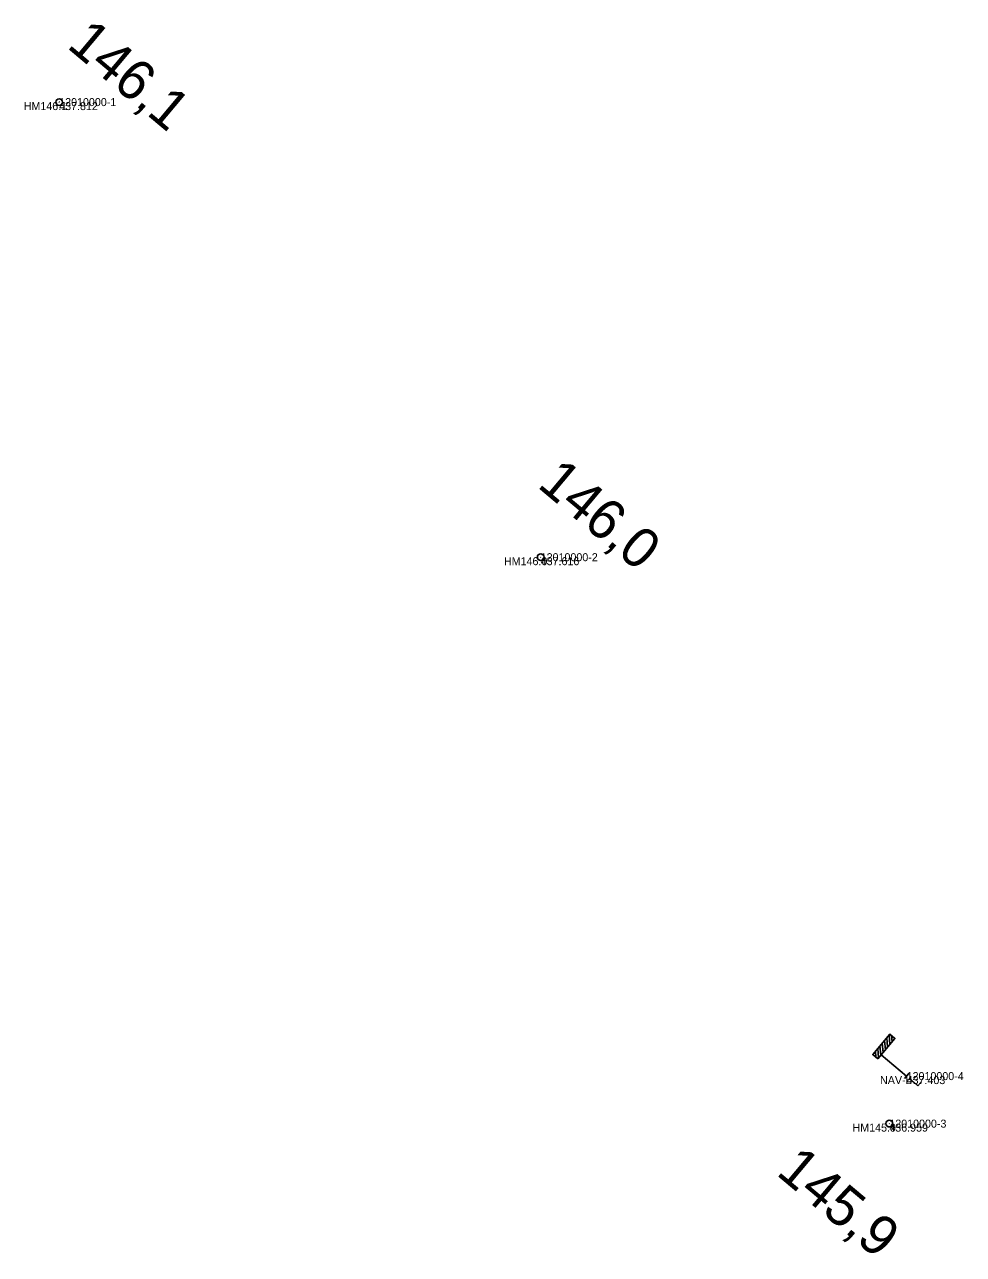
# Model space of a CAD drawing. Extents: x -653665 to -652742, y -1166300 to -1165487.
# Drawn here: x -652882.8 to -652741.9, y -1166299.9 to -1166115.5 of the extents above; entities that cross this region are included whole.
import ezdxf

# ---------------------------------------------------------------- set-up
doc = ezdxf.new("R2010")
doc.units = 0
for name, color, linetype in [('Vrstva 6', 7, 'Continuous'), ('Vrstva 60', 7, 'Continuous'), ('Vrstva 61', 7, 'Continuous'), ('Vrstva 62', 7, 'Continuous'), ('Vrstva 7', 7, 'Continuous')]:
    doc.layers.add(name, color=color, linetype=linetype)

msp = doc.modelspace()

# ---------------------------------------------------------------- linework, layer by layer
at = {"layer": 'Vrstva 6'}
for p, q in [((-652753.78, -1166267.81), (-652753.66, -1166269.22)), ((-652753.44, -1166267.4), (-652753.32, -1166268.81)), ((-652753.1, -1166266.99), (-652752.98, -1166268.4)), ((-652752.72, -1166267.09), (-652752.64, -1166268)), ((-652755.15, -1166269.43), (-652755.07, -1166270.34)), ((-652754.81, -1166269.03), (-652754.68, -1166270.43)), ((-652754.47, -1166268.62), (-652754.34, -1166270.03)), ((-652754.13, -1166268.21), (-652754, -1166269.62)), ((-652750.47, -1166273.16), (-652754.28, -1166269.96)), ((-652750.79, -1166273.54), (-652750.15, -1166272.77))]:
    msp.add_line(p, q, dxfattribs=at)
msp.add_lwpolyline([(-652754.8, -1166270.57), (-652755.56, -1166269.93), (-652752.99, -1166266.86), (-652752.23, -1166267.51)], close=True, dxfattribs=at)
at = {"layer": 'Vrstva 60'}
for p, q in [((-652877.65, -1166127.08), (-652877.65, -1166127.08)), ((-652805.39, -1166195.34), (-652805.39, -1166195.34)), ((-652750.47, -1166273.16), (-652750.47, -1166273.16)), ((-652753.07, -1166280.29), (-652753.07, -1166280.29))]:
    msp.add_line(p, q, dxfattribs=at)
at = {"layer": 'Vrstva 7'}
for p, q in [((-652877.69, -1166127.04), (-652877.61, -1166127.11)), ((-652805.43, -1166195.31), (-652805.35, -1166195.37)), ((-652753.11, -1166280.26), (-652753.04, -1166280.33))]:
    msp.add_line(p, q, dxfattribs=at)
for centre in [(-652877.65, -1166127.08), (-652805.39, -1166195.34), (-652753.07, -1166280.29)]:
    msp.add_circle(centre, 0.5, dxfattribs=at)

# ---------------------------------------------------------------- texts
at = {"layer": 'Vrstva 6'}
msp.add_text('L', height=1.5, rotation=50, dxfattribs=at).set_placement((-652748.87, -1166274.86))
at = {"layer": 'Vrstva 60'}
for s, p in [('12010000-1', (-652877.65, -1166127.68)), ('12010000-2', (-652805.39, -1166195.94)), ('12010000-4', (-652750.47, -1166273.76)), ('12010000-3', (-652753.07, -1166280.89))]:
    msp.add_text(s, height=1.2, dxfattribs=at).set_placement(p)
at = {"layer": 'Vrstva 61'}
for s, p in [('437.812', (-652877.65, -1166128.28)), ('437.616', (-652805.39, -1166196.54)), ('437.403', (-652750.47, -1166274.36)), ('436.959', (-652753.07, -1166281.49))]:
    msp.add_text(s, height=1.2, dxfattribs=at).set_placement(p)
at = {"layer": 'Vrstva 62'}
for s, p in [('HM146.1', (-652882.97, -1166128.28)), ('HM146.0', (-652810.9, -1166196.54)), ('NAV-L', (-652754.46, -1166274.36)), ('HM145.9', (-652758.59, -1166281.49))]:
    msp.add_text(s, height=1.2, dxfattribs=at).set_placement(p)
at = {"layer": 'Vrstva 7'}
for s, p in [('146,1', (-652876.66, -1166118.81)), ('146,0', (-652806.06, -1166184.71)), ('145,9', (-652770.21, -1166287.84))]:
    msp.add_text(s, height=6, rotation=320, dxfattribs=at).set_placement(p)

doc.saveas('drawing.dxf')
